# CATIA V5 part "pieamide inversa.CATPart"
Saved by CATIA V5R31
Part number: pieamide inversa
Bounding box of the stored display mesh (mm): x -150 to 150, y 0 to 3.3, z 0 to 175
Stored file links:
  C:\Users\189361\Desktop\piezas del comedero\piezas del comedero\pieamide inversa.CATPart
  C:\Users\189361\Desktop\paredes horizontales 2.0 1.CATPart
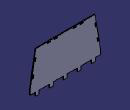
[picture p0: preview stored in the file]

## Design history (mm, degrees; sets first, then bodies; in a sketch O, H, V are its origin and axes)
Body1 (main body)
  Sketch1 on zx-plane, origin (0, 0, 0), H (-1, 0, 0), V (0, 0, 1)
    line L1 (-127.65, 15) -> (-150, 15)
    construction line L2 through (0, 0) direction (0, 1)
    line L3 (-150, 15) -> (-150, 35)
    point P1 (-127.65, 0)
    line L4 (-127.65, 15) -> (-127.65, 0)
    line L5 (-127.65, 0) -> (-112.35, 0)
    point P2 (-112.35, 15)
    line L6 (-112.35, 0) -> (-112.35, 15)
    line L7 (-112.35, 15) -> (-67.65, 15)
    point P3 (-67.65, 0)
    line L8 (-67.65, 15) -> (-67.65, 0)
    line L9 (-67.65, 0) -> (-52.35, 0)
    point P4 (-52.35, 15)
    line L10 (-52.35, 0) -> (-52.35, 15)
    point P5 (0, 20)
    construction line L11 (-120, 69.0879) -> (-120, 15.3646)
    construction line L12 (-60, 77.7749) -> (-60, 37.1309)
    point P6 (0, 20)
    line L13 (-52.35, 15) -> (-7.65, 15)
    point P7 (-7.65, 0)
    line L14 (-7.65, 15) -> (-7.65, 0)
    line L15 (-7.65, 0) -> (0, 0)
    point P8 (0, 20)
    point P9 (0, 20)
    point P10 (0, 0)
    point P11 (-127.65, 15)
    point P12 (-150, 15)
    point P13 (-150, 35)
    point P14 (-112.35, 0)
    point P15 (-67.65, 15)
    point P16 (-52.35, 0)
    point P17 (0, 20)
    point P18 (-120, 15.3646)
    point P19 (-120, 69.0879)
    point P20 (-60, 37.1309)
    point P21 (-60, 77.7749)
    point P22 (0, 20)
    point P23 (-7.65, 15)
    point P24 (0, 20)
    construction line L16 (0, 0) -> (0, 175)
    point P25 (0, 175)
    axis line L17 (0, 175) -> (-53, 175)
    point P26 (-53, 175)
    line L18 (0, 175) -> (-127, 175)
    point P27 (-127, 175)
    line L19 (-127, 175) -> (-150, 35)
    point P28 (0, 0)
    point P29 (127.65, 0)
    point P30 (112.35, 15)
    point P31 (67.65, 0)
    point P32 (52.35, 15)
    point P33 (0, 20)
    point P34 (120, 15.3646)
    point P35 (120, 69.0879)
    construction line L20 (120, 69.0879) -> (120, 15.3646)
    point P36 (60, 37.1309)
    point P37 (60, 77.7749)
    construction line L21 (60, 77.7749) -> (60, 37.1309)
    point P38 (0, 20)
    point P39 (7.65, 0)
    point P40 (0, 20)
    point P41 (0, 20)
    point P42 (0, 0)
    point P43 (127.65, 15)
    point P44 (150, 15)
    point P45 (150, 35)
    point P46 (112.35, 0)
    point P47 (67.65, 15)
    point P48 (52.35, 0)
    point P49 (0, 20)
    point P50 (0, 20)
    point P51 (7.65, 15)
    point P52 (0, 20)
    point P53 (0, 175)
    point P54 (53, 175)
    construction line L22 (0, 175) -> (53, 175)
    point P55 (127, 175)
    line L23 (127.65, 15) -> (150, 15)
    line L24 (150, 15) -> (150, 35)
    line L25 (127.65, 15) -> (127.65, 0)
    line L26 (127.65, 0) -> (112.35, 0)
    line L27 (112.35, 0) -> (112.35, 15)
    line L28 (112.35, 15) -> (67.65, 15)
    line L29 (67.65, 15) -> (67.65, 0)
    line L30 (67.65, 0) -> (52.35, 0)
    line L31 (52.35, 0) -> (52.35, 15)
    line L32 (52.35, 15) -> (7.65, 15)
    line L33 (7.65, 15) -> (7.65, 0)
    line L34 (7.65, 0) -> (0, 0)
    line L35 (0, 175) -> (127, 175)
    line L36 (127, 175) -> (150, 35)
    distance L11 L3 = 30
    distance L6 L11 = 7.65
    distance L12 L11 = 60
    distance L10 L12 = 7.65
    distance L2 L14 = 7.65
    length L14 = 15
    length L13 = 44.7
    length L3 = 20
    length L9 = 15.3
    length L16 = 175
    length L17 = 53
    length L18 = 127
    vertical: L3 L2, L4 L2, L6 L2, L8 L2, L10 L2, L11 L2, L12 L2, L16 V
    coincidence: P2 L1, P4 L1, P5 L2, O L2, L5 H, L13 L7, L15 H, P10 L2
    equal size: L4 L6, L6 L8, L8 L10, L9 L5, L10 L14, L14 L4
    symmetry: P5 P6 L2, P5 P8 L2, P6 P9 L2, P5 P17 L2, P6 P22 L2, P8 P24 L2, O P28 L16, P1 P29 L16, P2 P30 L16, P3 P31 L16, P4 P32 L16, P5 P33 L16, P18 P34 L16, P19 P35 L16, L11 L20 L16, P20 P36 L16, P21 P37 L16, L12 L21 L16, P6 P38 L16, P7 P39 L16, P8 P40 L16, P9 P41 L16, P10 P42 L16, P11 P43 L16, P12 P44 L16, P13 P45 L16, P14 P46 L16, P15 P47 L16, P16 P48 L16, P17 P49 L16, P22 P50 L16, P23 P51 L16, P24 P52 L16, P25 P53 L16, P26 P54 L16, L17 L22 L16, P27 P55 L16, L1 L23 L16, L3 L24 L16, L4 L25 L16, L5 L26 L16, L6 L27 L16, L7 L28 L16, L8 L29 L16, L9 L30 L16, L10 L31 L16, L13 L32 L16, L14 L33 L16, L15 L34 L16, L18 L35 L16, L19 L36 L16
    perpendicularity: L6 L7
    horizontal: L17 H, L18 H
  Pad1: profile Sketch1, direction (0, 1, 0), length 3.3
  Sketch2 on end face of Pad1, origin (0, 3.3, 0), H (-1, 0, 0), V (0, 0, 1)
    point P1 (-47.5, 172)
    line L1 (-47.5, 172) -> (-32.5, 172)
    line L2 (-32.5, 172) -> (-32.5, 168.7)
    line L3 (-32.5, 168.7) -> (-47.5, 168.7)
    line L4 (-47.5, 168.7) -> (-47.5, 172)
    point P2 (-32.5, 172)
    point P3 (-32.5, 168.7)
    point P4 (-47.5, 168.7)
    construction line L5 (-40, 200.409) -> (-40, 181.2846)
    point P5 (-40, 200.409)
    point P6 (-40, 181.2846)
    reference projected line E1 (0, 175) -> (-127, 175) from edge [face of Pad1 from Sketch1.L18 | end face of Pad1]
    point P7 (47.5, 172)
    point P8 (32.5, 172)
    point P9 (32.5, 168.7)
    point P10 (47.5, 168.7)
    line L6 (47.5, 172) -> (32.5, 172)
    line L7 (32.5, 172) -> (32.5, 168.7)
    line L8 (32.5, 168.7) -> (47.5, 168.7)
    line L9 (47.5, 168.7) -> (47.5, 172)
    point P11 (-141.3626, 69.0701)
    line L10 (-141.3626, 69.0701) -> (-138.1062, 68.5351)
    point P12 (-138.1062, 68.5351)
    line L11 (-138.1062, 68.5351) -> (-135.6745, 83.3367)
    point P13 (-135.6745, 83.3367)
    line L12 (-135.6745, 83.3367) -> (-138.9309, 83.8717)
    point P14 (-138.9309, 83.8717)
    line L13 (-138.9309, 83.8717) -> (-141.3626, 69.0701)
    reference projected line E2 (-123.8601, 194.1122) -> (-150, 35) from edge [face of Pad1 from Sketch1.L19 | end face of Pad1]
    construction line L14 (-122.5963, 164.7941) -> (-143.6709, 36.5137)
    point P18 (-146.6312, 37)
    construction line L15 (-146.6312, 37) -> (-125.5566, 165.2804)
    construction line L16 (-143.6709, 36.5137) -> (-146.6312, 37)
    construction line L17 (-125.5566, 165.2804) -> (-122.5963, 164.7941)
    reference projected point E3 (-150, 35) from vertex [face of Pad1 from Sketch1.L3 | end face of Pad1 | face of Pad1 from Sketch1.L19]
    construction line L18 (-117.5, 172) -> (117.5, 172)
    construction line L19 (117.5, 172) -> (117.5, 169)
    construction line L20 (117.5, 169) -> (-117.5, 169)
    construction line L21 (-117.5, 169) -> (-117.5, 172)
    point P23 (40, 181.2846)
    point P24 (40, 200.409)
    construction line L22 (40, 200.409) -> (40, 181.2846)
    construction line L23 (-162.6915, 80.1747) -> (-181.1718, 83.2107)
    construction line L24 (-159.9601, 110.1281) -> (-179.3888, 113.32)
    point P29 (-129.2041, 143.078)
    point P30 (-131.6358, 128.2764)
    line L25 (-131.6358, 128.2764) -> (-129.2041, 143.078)
    point P31 (-125.9478, 142.543)
    line L26 (-129.2041, 143.078) -> (-125.9478, 142.543)
    point P32 (-128.3795, 127.7415)
    line L27 (-125.9478, 142.543) -> (-128.3795, 127.7415)
    line L28 (-128.3795, 127.7415) -> (-131.6358, 128.2764)
    point P33 (135.6745, 83.3367)
    point P34 (138.1062, 68.5351)
    line L29 (138.1062, 68.5351) -> (135.6745, 83.3367)
    point P35 (141.3626, 69.0701)
    line L30 (141.3626, 69.0701) -> (138.1062, 68.5351)
    point P36 (138.9309, 83.8717)
    line L31 (138.9309, 83.8717) -> (141.3626, 69.0701)
    line L32 (135.6745, 83.3367) -> (138.9309, 83.8717)
    point P37 (131.6358, 128.2764)
    point P38 (128.3795, 127.7415)
    line L33 (128.3795, 127.7415) -> (131.6358, 128.2764)
    point P39 (129.2041, 143.078)
    line L34 (131.6358, 128.2764) -> (129.2041, 143.078)
    point P40 (125.9478, 142.543)
    line L35 (125.9478, 142.543) -> (128.3795, 127.7415)
    line L36 (129.2041, 143.078) -> (125.9478, 142.543)
    axis line L37 (-55, 181.2846) -> (-55, 200.409)
    point P43 (-77.5, 172)
    point P44 (-62.5, 172)
    line L38 (-62.5, 172) -> (-77.5, 172)
    point P45 (-62.5, 168.7)
    line L39 (-62.5, 168.7) -> (-62.5, 172)
    point P46 (-77.5, 168.7)
    line L40 (-77.5, 168.7) -> (-62.5, 168.7)
    line L41 (-77.5, 172) -> (-77.5, 168.7)
    point P47 (77.5, 172)
    point P48 (62.5, 172)
    line L42 (62.5, 172) -> (77.5, 172)
    point P49 (62.5, 168.7)
    point P50 (77.5, 168.7)
    line L43 (77.5, 168.7) -> (62.5, 168.7)
    line L44 (77.5, 172) -> (77.5, 168.7)
    line L45 (62.5, 168.7) -> (62.5, 172)
    length L1 = 15
    length L4 = 3.3
    distance L2 L5 = 7.5
    distance L5 V = 40
    distance L1 E1 = 3
    length L13 = 15
    length L12 = 3.3
    distance L13 E2 = 3
    length L16 = 3
    distance P18 E3 V = 2
    length L15 = 130
    length L21 = 3
    distance L10 L23 = 7.5
    distance L23 L16 = 40
    distance L23 L24 = 30
    distance L37 L5 = 15
    distance L41 L21 = 40
    distance L19 L44 = 40
    length L18 = 235 (reference)
    horizontal: L1 H, L3 H, L18 H, L20 H
    vertical: L2 V, L4 V, L5 V, L19 V, L21 V, L37 V
    symmetry: P1 P7 V, P2 P8 V, P3 P9 V, P4 P10 V, L1 L6 V, L2 L7 V, L3 L8 V, L4 L9 V, P6 P23 V, P5 P24 V, L5 L22 V, P11 P29 L24, P14 P30 L24, L13 L25 L24, P12 P31 L24, L10 L26 L24, P13 P32 L24, L11 L27 L24, L12 L28 L24, P13 P33 V, P12 P34 V, L11 L29 V, P11 P35 V, L10 L30 V, P14 P36 V, L13 L31 V, L12 L32 V, P30 P37 V, P32 P38 V, L28 L33 V, P29 P39 V, L25 L34 V, P31 P40 V, L27 L35 V, L26 L36 V, P2 P43 L37, P1 P44 L37, L1 L38 L37, P4 P45 L37, L4 L39 L37, P3 P46 L37, L3 L40 L37, L2 L41 L37, P43 P47 V, P44 P48 V, L38 L42 V, P45 P49 V, P46 P50 V, L40 L43 V, L41 L44 V, L39 L45 V
    perpendicularity: L11 L10, L13 L10, L16 L15, L16 L14, L14 L17, L15 L17
    parallelism: L12 L10
    coincidence: L15 L13, L1 L18
  Pocket1: profile Sketch2, direction (0, -1, 0), length 3.3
